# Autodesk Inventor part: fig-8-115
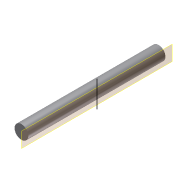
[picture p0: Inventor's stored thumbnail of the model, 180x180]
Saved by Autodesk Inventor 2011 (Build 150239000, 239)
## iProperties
Created: 2007-02
Part Number: fig-8-115
Document SubType Name: Modeling
Designer: Administrator
Density: 1 g/cm^3
Author: Administrator
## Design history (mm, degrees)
node "Sketch1"
sketch "Sketch2"
  geometry: C1 r 5 at (0, 0); 1 further point
  constraints: 1 centre point, 1 coincident, 1 other
  dimensions: "d0" = 10 diameter of C1
extrude "Extrusion1" new body sketch "Sketch2" stored distance "d1" = 100; taper "d2" = 0 deg
workplane "Work Plane1"
sketch "Sketch3"
  geometry: L1 (0, 11)-(0, -8)
  constraints: 2 end point, 1 vertical
body "Solid1"
